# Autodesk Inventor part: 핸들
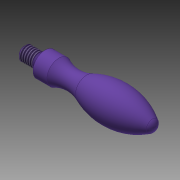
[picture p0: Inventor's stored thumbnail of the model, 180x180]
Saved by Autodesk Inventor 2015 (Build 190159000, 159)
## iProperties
Created: 2019-10
Part Number: 핸들
Material: 스테인리스강
Document SubType Name: Modeling
Designer: mduedu
Density: 1 g/cm^3
Appearance: 보라색
Author: mduedu
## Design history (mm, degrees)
sketch "스케치1"
  geometry: L1 (0, 0)-(0, 2); L2 (0, 2)-(4.35, 2); L3 (6, 1.45)-(6, 3.5); L4 (6, 3.5)-(10, 3.5); L5 (0, 0)-(38, 0); L6 (4.9, 1.45)-(6, 1.45); L7 (4.9, 1.45)-(4.35, 2); A1 r 9.5 centre (14.243, 12) between (10, 3.5) and (18.07, 3.305); A2 r 20 centre (26.128, -15) between (37.049, 1.754) and (18.07, 3.305); A3 r 2.094 centre (35.906, 0) between (38, 0) and (37.049, 1.754)
  constraints: 14 end point, 6 point on circle, 3 centre point, 3 parallel, 2 tangent, 1 perpendicular, 1 point on line, 1 vertical
  dimensions: "d1" = 4 diameter of L2 L5; "d2" = 7 diameter of L4 L5; "d4" = 4 distance of L3.end L4.end; "d5" = 5 dimension on A1 L5; "d6" = 9.5 radius of A1; "d7" = 10 dimension on A2 L5; "d8" = 20 radius of A2; "d15" = 6 distance between parallel lines of L1 L3; "d16" = 38 distance from line of L5.end L1; "d17" = 2.9 diameter of L6 L5 (computed from d1); "d19" = 1.1 distance of L6.start L3.start; "d20" = 135 deg angle of L7 L6
revolve "회전1" sketch "스케치1" stored, may be unused: angle "d9" = 90 deg
feature "스레드1" dims "d10" = 5, "d11" = 0
chamfer "모따기1" distance "d12" = 0.5; stored, may be unused: second distance "d13" = 2, angle "d14" = 45 deg
fillet "모깎기1" dims "d21" = 0.4
node "솔리드1"
